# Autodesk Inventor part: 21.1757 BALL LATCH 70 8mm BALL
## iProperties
Created: 2007-03
Part Number: 21.1757 BALL LATCH 70 8mm BALL
Document SubType Name: Modeling
Designer: Andy Moles
Material: Steel
Mass: 2.10445 g
Surface Area: 2.01062 cm^2
Volume: 0.268083 cm^3
Density: 7.85 g/cm^3
Author: Andy Moles
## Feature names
1. Revolution1
